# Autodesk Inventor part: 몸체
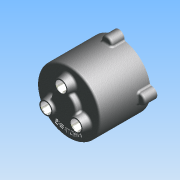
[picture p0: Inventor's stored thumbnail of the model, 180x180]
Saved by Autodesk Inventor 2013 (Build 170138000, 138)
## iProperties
Created: 2012-05
Part Number: 몸체
Document SubType Name: 모델링
Designer: SeoGD™
Material: 알루미늄 6061
Mass: 475.555 g
Surface Area: 687.659 cm^2
Volume: 175.481 cm^3
Density: 2.71 g/cm^3
변환 표준: STEP AP214IS
파일 이름: C:\Users\SeoGD\Desktop\?쒗뿕\紐몄껜.stp
전처리기: Build: 253, Release: 2010 SP1 - Date: Wed 07/29/2009
전송 단위: 밀리미터
불확실성: 0.01
Author: SeoGD™
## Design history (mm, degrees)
sketch "스케치2"
  geometry: C1 r 50 at (0, 0); 1 further point
  constraints: 1 centre point, 1 coincident
  dimensions: "d9" = 100 diameter of C1
extrude "돌출2" new body sketch "스케치2" distance "d10" = 80; taper "d11" = 0 deg
feature "쉘1" dims "d12" = 5
sketch "스케치3" dims "d13" = 55
  geometry: C1 r 7.5 at (0, 27.5); C2 r 12.5 at (0, 27.5); 2 further points
  constraints: 2 centre point, 2 coincident, 2 vertical alignment, 2 other
  dimensions: "d14" = 15 diameter of C1; "d15" = 25 diameter of C2
extrude "돌출3" join sketch "스케치3" distance "d16" = 12; taper "d17" = -10 deg
hole "구멍2" diameter "d20" = 15; stored, may be unused: countersink angle "d24" = 90 deg, drill point angle "d26" = 118 deg; dims "d18" = 10, "d19" = 10, "d21" = 6, "d22" = 4, "d23" = 2, "d25" = 15
chamfer "모따기1" distance "d27" = 1; stored, may be unused: second distance "d28" = 2, angle "d29" = 45 deg
sketch "스케치4"
  geometry: L1 (0, 0)-(0, 88); L2 (0, 70)-(13.16, 70); L3 (-45, 75)-(45, 75) reference; L4 (-50, 80)-(50, 80) reference; L5 (13.16, 70)-(14.5, 75); L6 (20, 80)-(20, 88); L7 (20, 88)-(0, 88); L8 (20, 80)-(14.5, 75)
  constraints: 12 end point, 3 point on line, 2 perpendicular, 1 vertical
  dimensions: "d34" = 40 diameter of L6 L1; "d35" = 105 deg angle of L5 L3; "d36" = 5 distance between parallel lines of L2 L3; "d37" = 8 distance between parallel lines of L7 L4; "d51" = 29 diameter of L5.end L1
revolve "회전1" sketch "스케치4" stored, may be unused: angle "d38" = 90 deg
hole "구멍3" diameter "d41" = 15; stored, may be unused: countersink angle "d45" = 90 deg, drill point angle "d47" = 0 deg; dims "d39" = 10, "d40" = 10, "d42" = 6, "d43" = 22, "d44" = 13, "d46" = 15
chamfer "모따기2" distance "d48" = 1; stored, may be unused: second distance "d49" = 2, angle "d50" = 45 deg
fillet "모깎기1" dims "d52" = 3
fillet "모깎기2" dims "d53" = 3, "d72" = 0.2
sketch "스케치5"
  geometry: A1 r 50 centre (0, 0) between (50, 0) and (-8.074, 49.344) reference; A2 r 8.5 centre (0, 52) between (8.074, 49.344) and (-8.074, 49.344); 1 further point
  constraints: 5 point on circle, 1 centre point, 1 horizontal alignment
  dimensions: "d54" = 90 deg dimension on point (0, 0) A2.centre A1.start; "d55" = 52 distance of A2.centre point (0, 0); "d56" = 17 diameter of A2
extrude "돌출4" join sketch "스케치5" distance "d57" = 20; taper "d58" = 0 deg
fillet "모깎기3" dims "d59" = 3
hole "구멍4" diameter "d62" = 4.134; stored, may be unused: countersink angle "d66" = 90 deg, drill point angle "d68" = 118 deg; dims "d60" = 10, "d61" = 10, "d63" = 12, "d64" = 22, "d65" = 13, "d67" = 15
sketch "스케치6"
  geometry: C1 r 47 at (0, 0) reference; C2 r 42.5 at (0, 0); 1 further point
  constraints: 1 centre point, 1 coincident, 1 other
  dimensions: "d73" = 85 diameter of C2
feature "엠보싱1" sketch "스케치6" dims "d74" = 1, "d75" = 0
node "솔리드1"
node "솔리드 본체"
node "곡면 본체"
pattern_circular "원형 패턴1" dims "d31" = 360 deg
pattern_circular "원형 패턴2" dims "d70" = 360 deg
node "솔리드2"
